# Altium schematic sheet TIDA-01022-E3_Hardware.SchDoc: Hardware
size 431 x 279 mm; Date: Not shown in title block; ApprovedBy: Not shown in title block; CheckedBy: Not shown in title block; Author: Not shown in title block; CompanyName: Not shown in title block; DrawnBy: Avinash N; Engineer: Not shown in title block; Organization: Not shown in title block; Address1: Not shown in title block; Address2: Not shown in title block; Address3: Not shown in title block; Address4: Not shown in title block; DocumentNumber: 1; Revision: Use project parameter SCH_Rev; SheetNumber: 26; SheetTotal: 26; PageSetup: Record=PageOptions¦CenterHorizontal=True¦CenterVertical=True¦PrintScale=1.00¦XCorrection=1.00¦YCorrection=1.00¦PrintKind=0¦BorderSize=5000000¦LeftOffset=0¦BottomOffset=0¦Orientation=2¦PaperLength=1000¦PaperWidth=1000¦Scale=100¦PaperSource=15¦PrintQuality=600¦MediaType=1¦DitherType=10¦PaperKind=Letter¦PrintScaleMode=1
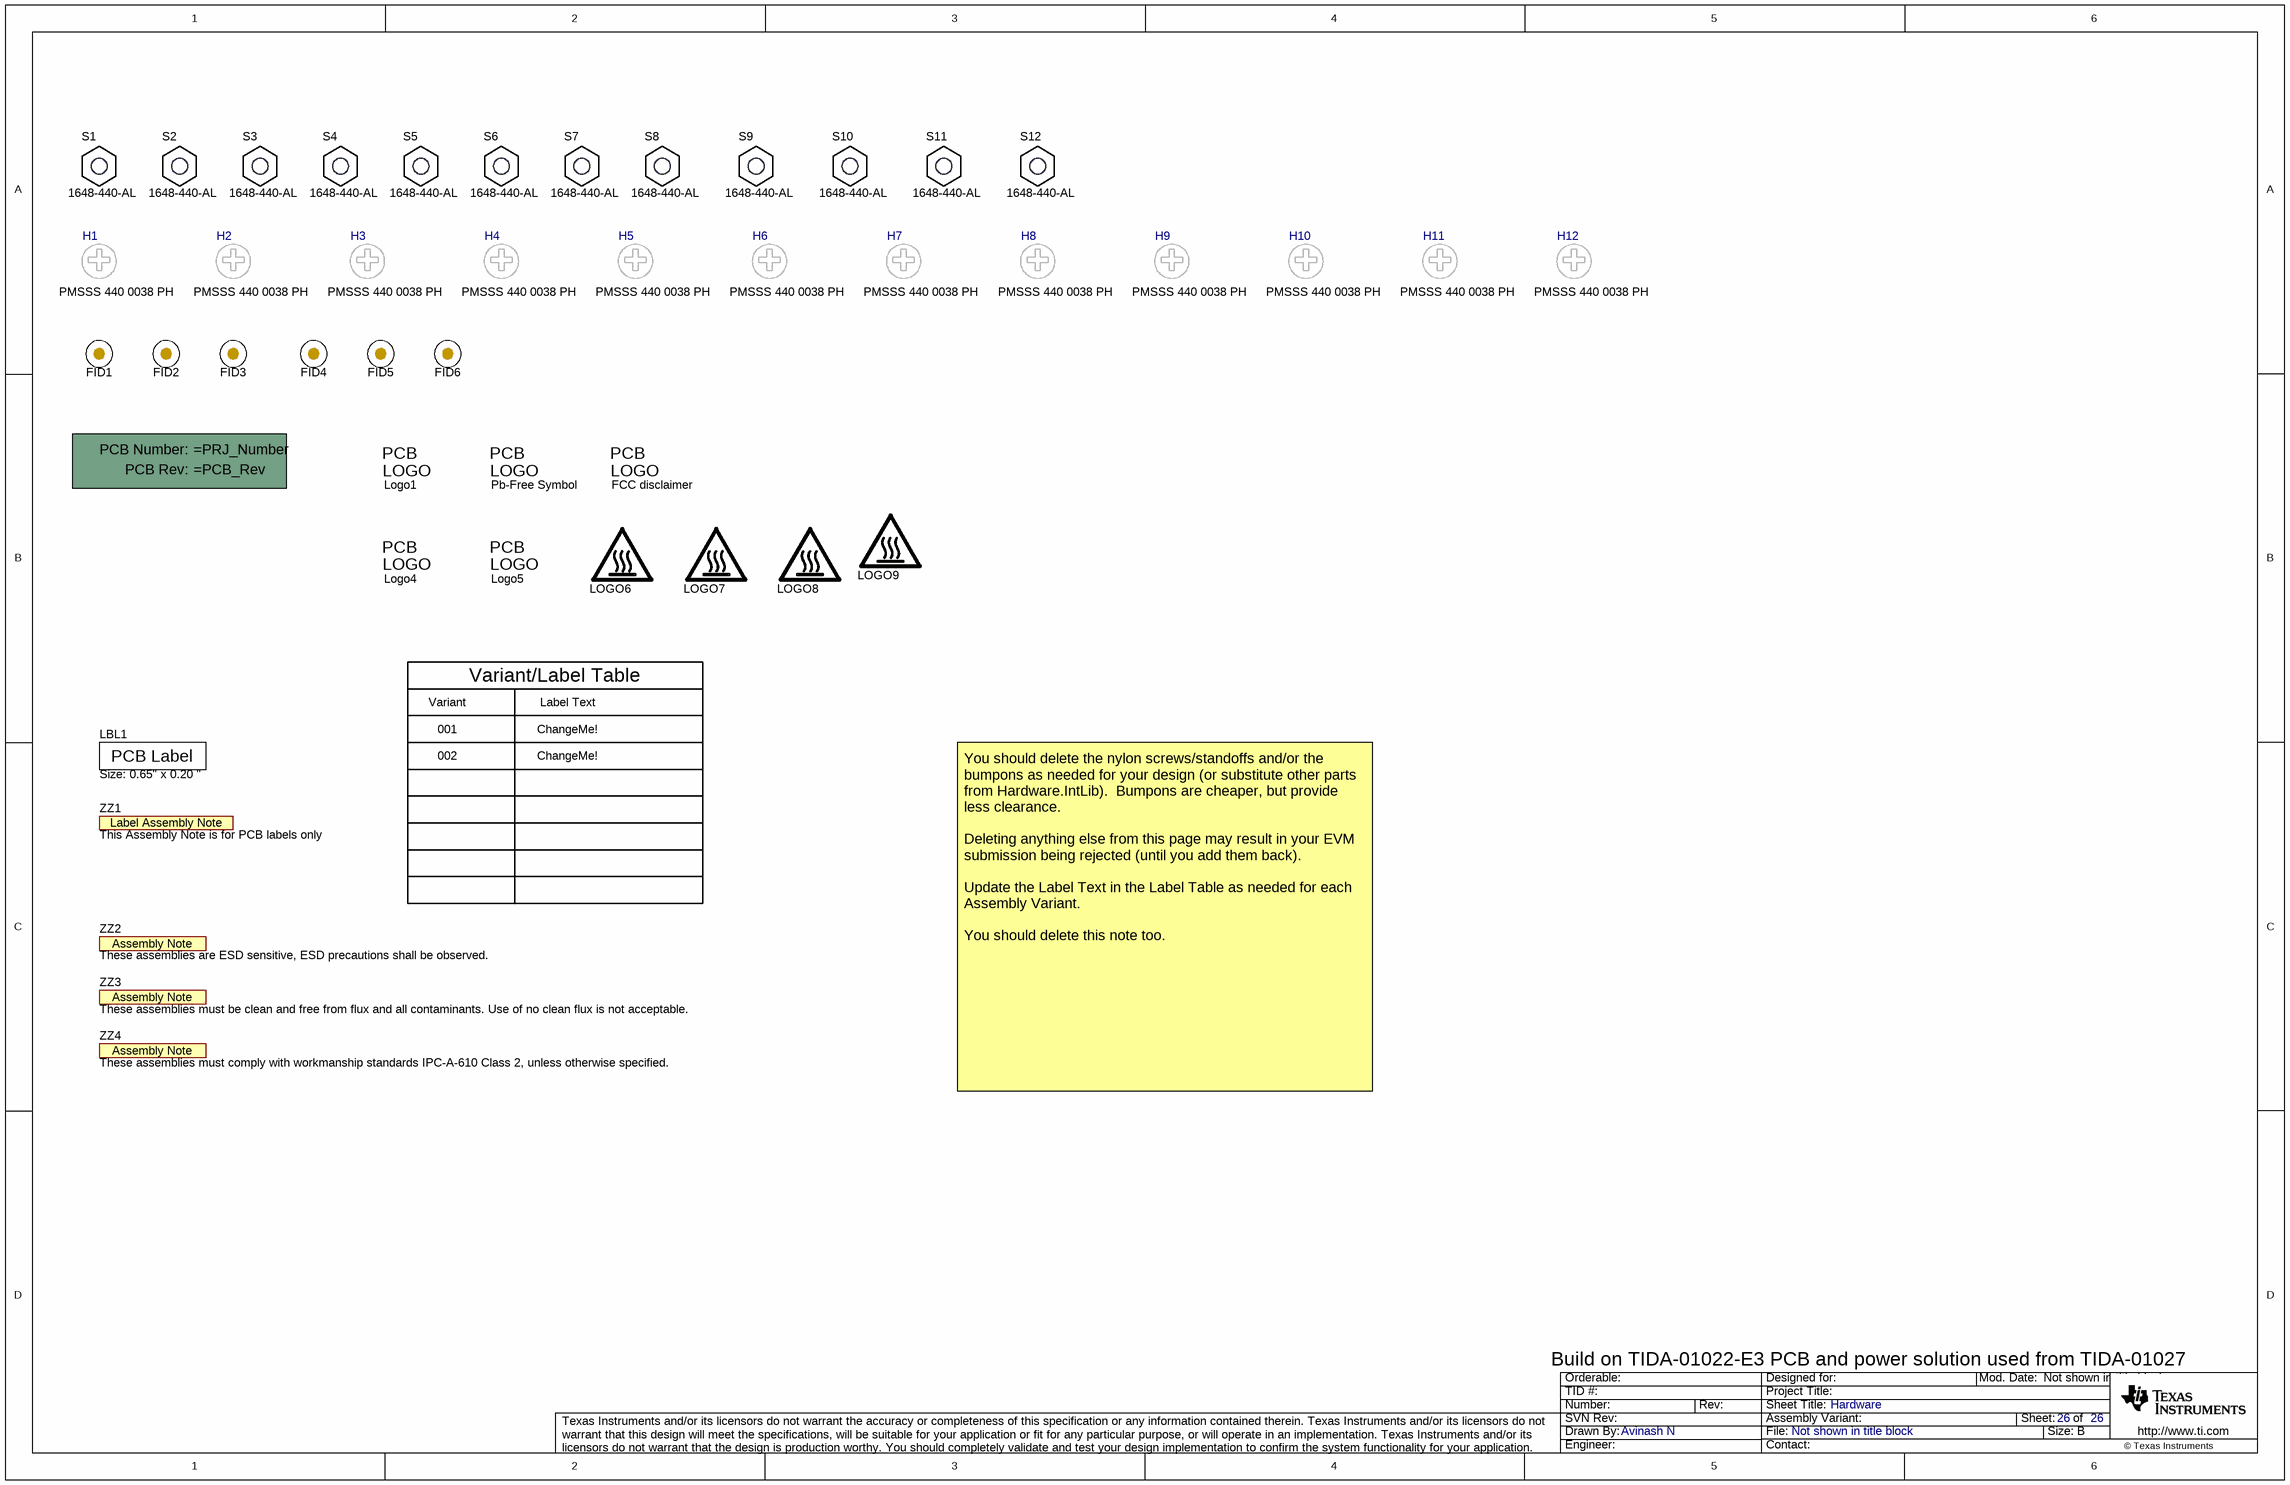
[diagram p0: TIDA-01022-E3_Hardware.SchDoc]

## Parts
!PCB1  Printed Circuit Board  (value not drawn)  (mechanical)
FID1  Fiducial  [Fiducial10-20]  (value not drawn)
FID2  Fiducial  [Fiducial10-20]  (value not drawn)
FID3  Fiducial  [Fiducial10-20]  (value not drawn)
FID4  Fiducial  [Fiducial10-20]  (value not drawn)
FID5  Fiducial  [Fiducial10-20]  (value not drawn)
FID6  Fiducial  [Fiducial10-20]  (value not drawn)
H1  PMSSS 440 0038 PH  [BuildingFastener_MPMS_003_0005_PH]  (mechanical)
H2  PMSSS 440 0038 PH  [BuildingFastener_MPMS_003_0005_PH]  (mechanical)
H3  PMSSS 440 0038 PH  [BuildingFastener_MPMS_003_0005_PH]  (mechanical)
H4  PMSSS 440 0038 PH  [BuildingFastener_MPMS_003_0005_PH]  (mechanical)
H5  PMSSS 440 0038 PH  [BuildingFastener_MPMS_003_0005_PH]  (mechanical)
H6  PMSSS 440 0038 PH  [BuildingFastener_MPMS_003_0005_PH]  (mechanical)
H7  PMSSS 440 0038 PH  [BuildingFastener_MPMS_003_0005_PH]  (mechanical)
H8  PMSSS 440 0038 PH  [BuildingFastener_MPMS_003_0005_PH]  (mechanical)
H9  PMSSS 440 0038 PH  [BuildingFastener_MPMS_003_0005_PH]  (mechanical)
H10  PMSSS 440 0038 PH  [BuildingFastener_MPMS_003_0005_PH]  (mechanical)
H11  PMSSS 440 0038 PH  [BuildingFastener_MPMS_003_0005_PH]  (mechanical)
H12  PMSSS 440 0038 PH  [BuildingFastener_MPMS_003_0005_PH]  (mechanical)
LBL1  Size: 0.65" x 0.20 "  [Label_650x200]
Logo1  ESD Susceptible  [ESD_Overlay_Large]  (value not drawn)  (no BOM)
Logo2  Pb-Free Symbol  [Pb-Free_Overlay_Small]  (no BOM)
Logo3  FCC disclaimer  [FCC_disclaimer]  (no BOM)
Logo4  EU RoHS Exempt Logo  [EURoHS_Exempt_60mil]  (value not drawn)  (no BOM)
Logo5  CAUTION.  READ USER GUIDE BEFORE USE  [IEC_Caution_Medium]  (value not drawn)  (no BOM)
LOGO6  CAUTION HOT SURFACE  [IEC_HotSurface_small]  (value not drawn)  (no BOM)
LOGO7  CAUTION HOT SURFACE  [IEC_HotSurface_small]  (value not drawn)  (no BOM)
LOGO8  CAUTION HOT SURFACE  [IEC_HotSurface_small]  (value not drawn)  (no BOM)
LOGO9  CAUTION HOT SURFACE  [IEC_HotSurface_small]  (value not drawn)  (no BOM)
S1  1648-440-AL  [TCBS-6-01]
S2  1648-440-AL  [TCBS-6-01]
S3  1648-440-AL  [TCBS-6-01]
S4  1648-440-AL  [TCBS-6-01]
S5  1648-440-AL  [TCBS-6-01]
S6  1648-440-AL  [TCBS-6-01]
S7  1648-440-AL  [TCBS-6-01]
S8  1648-440-AL  [TCBS-6-01]
S9  1648-440-AL  [TCBS-6-01]
S10  1648-440-AL  [TCBS-6-01]
S11  1648-440-AL  [TCBS-6-01]
S12  1648-440-AL  [TCBS-6-01]
ZZ1  This Assembly Note is for PCB labels only  [AssemblyNoteLabel]  (no BOM)
ZZ2  These assemblies are ESD sensitive, ESD precautions shall be observed.  [AssemblyNote]  (no BOM)
ZZ3  These assemblies must be clean and free from flux and all contaminants. Use of no clean flux is not acceptable.  [AssemblyNote]  (no BOM)
ZZ4  These assemblies must comply with workmanship standards IPC-A-610 Class 2, unless otherwise specified.  [AssemblyNote]  (no BOM)

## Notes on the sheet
- Variant
- Variant/Label Table
- Label Text
- 001
- 002
- ChangeMe!
- You should delete the nylon screws/standoffs and/or the bumpons as needed for your design (or substitute other parts from Hardware.IntLib).  Bumpons are cheaper, but provide less clearance.
  Deleting anything else from this page may result in your EVM submission being rejected (until you add them back).
  Update the Label Text in the Label Table as needed for each Assembly Variant.
  You should delete this note too.
- Build on TIDA-01022-E3 PCB and power solution used from TIDA-01027

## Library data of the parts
!PCB1 = PCB: Manufacturer: Any; SymbolCreator: a0412235
FID1-FID6 = Fiducial: Fiducial mark.  There is nothing to buy or mount.; SymbolCreator: codlsc
H1-H12 = MPMS 003 0005 PH: MACHINE SCREW PAN PHILLIPS 4-40; Manufacturer: B&F Fastener Supply; CompType: Hardware
LBL1 = THT-14-423-10: Thermal Transfer Printable Labels, 0.650" W x 0.200" H - 10,000 per roll; Manufacturer: Brady; SymbolCreator: a0412235; CompType: Label
Logo1 = ESD_Susceptible: ESD Susceptible Symbol; SymbolCreator: a0412235
Logo2 = Pb-Free: SymbolCreator: a0412235
Logo3 = FCC_disclaimer: SymbolCreator: codlsc
Logo4 = EURoHS_Exempt: SymbolCreator: a0412235
Logo5 = IEC_Caution: IEC 61010-1 Caution Warning; SymbolCreator: a0412235
LOGO6-LOGO9 = IEC_HotSurface: IEC 61010-1 Hot Surface Warning; SymbolCreator: a0412235
S1-S12 = TCBS-6-01: 3/16 RD X 1-3/16 LENGTH; Manufacturer: RAF Electronic Hardware; CompType: Standoff; SymbolCreator: a0412235
ZZ1 = AssemblyNoteLabel: SymbolCreator: a0412235
ZZ2-ZZ4 = AssemblyNote: SymbolCreator: codlsc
